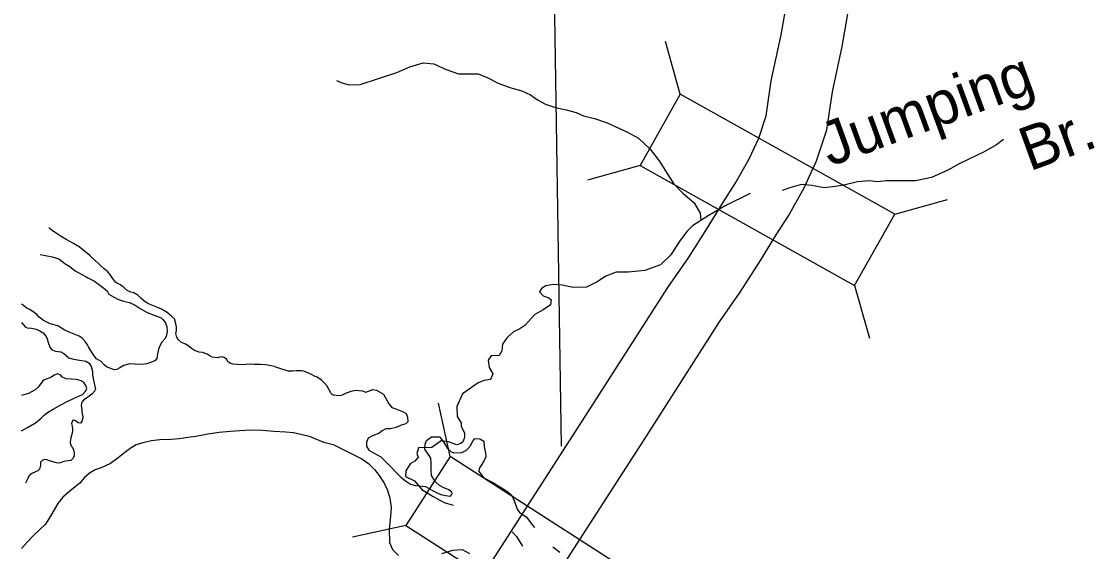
# Model space of a CAD drawing. Extents: x -492261 to -432772, y 1441225 to 1452922.
# Drawn here: x -459921.4 to -459791.8, y 1451627.3 to 1451691.4 of the extents above; entities that cross this region are included whole.
import ezdxf

# ---------------------------------------------------------------- set-up
doc = ezdxf.new("R2010")
doc.units = 0
doc.layers.add('Default', color=7, linetype='Continuous')

msp = doc.modelspace()

# ---------------------------------------------------------------- linework, layer by layer
at = {"layer": 'Default'}
for p, q in [((-459841.83, 1451682.61), (-459843.61, 1451688.97)), ((-459846.67, 1451673.98), (-459853.03, 1451672.2)), ((-459815.93, 1451668.07), (-459809.57, 1451669.86)), ((-459820.77, 1451659.44), (-459818.99, 1451653.09)), ((-459869.64, 1451638.77), (-459871.05, 1451645.22)), ((-459874.99, 1451630.44), (-459881.44, 1451629.03))]:
    msp.add_line(p, q, dxfattribs=at)
for points in [[(-459856.2, 1451640.04), (-459857.13, 1451699.95), (-459857.07, 1451700.88), (-459857.88, 1451764.63), (-459857.72, 1451765.56), (-459857.84, 1451829.92), (-459857.78, 1451831.18), (-459858.68, 1451894.27)], [(-459880.67, 1451586.99), (-459870.99, 1451602.58), (-459862.3, 1451615.79), (-459845.93, 1451641.25), (-459837.1, 1451655.06), (-459834.61, 1451658.63), (-459832.16, 1451662.47), (-459830.27, 1451665.59), (-459828.78, 1451667.87), (-459826.87, 1451671.27), (-459825.36, 1451674.52), (-459824.12, 1451678.26), (-459823.46, 1451682.88), (-459822.28, 1451688.35), (-459819.61, 1451703.72), (-459814.06, 1451738.82), (-459808.56, 1451770.84), (-459804.54, 1451796.57), (-459800.12, 1451821.52)], [(-459887.04, 1451590.94), (-459877.31, 1451606.62), (-459868.59, 1451619.88), (-459852.25, 1451645.3), (-459843.34, 1451659.22), (-459840.85, 1451662.79), (-459838.53, 1451666.43), (-459836.62, 1451669.59), (-459835.19, 1451671.77), (-459833.55, 1451674.68), (-459832.35, 1451677.28), (-459831.45, 1451679.99), (-459830.85, 1451684.2), (-459829.65, 1451689.78), (-459827, 1451704.95), (-459821.46, 1451740.04), (-459815.96, 1451772.06), (-459811.94, 1451797.8)], [(-459883.37, 1451684.26), (-459882.71, 1451683.95), (-459881.83, 1451683.72), (-459880.51, 1451683.78), (-459876.07, 1451685.22), (-459874.51, 1451685.88), (-459872.88, 1451686.4), (-459871.6, 1451686.25), (-459870.11, 1451685.56), (-459868.64, 1451685.07), (-459866.27, 1451685.06), (-459865.18, 1451684.61), (-459863.82, 1451683.91), (-459862.43, 1451683.4), (-459860.99, 1451682.98), (-459859.93, 1451682.53), (-459859.09, 1451681.9), (-459858.1, 1451681.4), (-459856.89, 1451680.98), (-459855.61, 1451680.71), (-459854.43, 1451680.36), (-459853.52, 1451679.98), (-459852.19, 1451679.66), (-459850.65, 1451679.13), (-459848.2, 1451678.01), (-459846.88, 1451677.26), (-459845.47, 1451675.94), (-459844.39, 1451674.52), (-459842.67, 1451671.78), (-459841.51, 1451670.6), (-459840.16, 1451669.46), (-459839.43, 1451668.22), (-459839.34, 1451667.32)], [(-459802.78, 1451677.12), (-459803.64, 1451676.45), (-459805.14, 1451675.61), (-459808.16, 1451674.18), (-459809.51, 1451673.4), (-459811.47, 1451672.52), (-459813.43, 1451672.1), (-459816.98, 1451672.11), (-459818, 1451672.01), (-459818.98, 1451672.11), (-459820.43, 1451671.97), (-459821.92, 1451671.61), (-459823.11, 1451671.41), (-459824.46, 1451671.27), (-459825.96, 1451671.54), (-459827.19, 1451671.66), (-459828.61, 1451671.27), (-459829.51, 1451670.95)], [(-459833.39, 1451670.58), (-459836.42, 1451669.1), (-459838.46, 1451667.89), (-459840.34, 1451666.67), (-459841.05, 1451665.98), (-459841.99, 1451664.73), (-459842.98, 1451663.17), (-459844.23, 1451661.97), (-459846.11, 1451661.27), (-459848.13, 1451661.07), (-459849.6, 1451661.08), (-459850.84, 1451660.6), (-459851.87, 1451659.9), (-459853.18, 1451659.26), (-459854.78, 1451659.23), (-459856.09, 1451659.49), (-459857.19, 1451659.57), (-459858.06, 1451659.4), (-459858.6, 1451659.08), (-459858.84, 1451658.7), (-459858.41, 1451658.21), (-459857.72, 1451657.97), (-459857.44, 1451657.71), (-459857.5, 1451657.13), (-459858.39, 1451656.51), (-459859.4, 1451655.93), (-459860.62, 1451654.62), (-459861.21, 1451654.23), (-459861.97, 1451653.84), (-459862.75, 1451653.16), (-459863.31, 1451652.37), (-459863.39, 1451651.57), (-459863.73, 1451650.99), (-459864.67, 1451650.96), (-459865.06, 1451650.43), (-459864.92, 1451649.55), (-459864.5, 1451648.79), (-459864.75, 1451648.1), (-459865.55, 1451647.96), (-459866.27, 1451647.69), (-459868.14, 1451646.34), (-459868.84, 1451644.82)], [(-459883.99, 1451646.38), (-459884.5, 1451647.26), (-459884.8, 1451647.64), (-459885.17, 1451648), (-459885.71, 1451648.35), (-459885.94, 1451648.45), (-459886.37, 1451648.69), (-459887.33, 1451649.08), (-459887.6, 1451649.14), (-459887.96, 1451649.12), (-459888.23, 1451649.12), (-459888.64, 1451649.1), (-459889.2, 1451649.09), (-459890.7, 1451649.58), (-459890.91, 1451649.65), (-459891.25, 1451649.74), (-459891.66, 1451649.83), (-459891.92, 1451649.87), (-459892.55, 1451649.89), (-459893.3, 1451649.91), (-459893.76, 1451649.93), (-459894.27, 1451649.92), (-459894.8, 1451649.87), (-459895.31, 1451649.9), (-459895.88, 1451649.95), (-459896.22, 1451650.06), (-459896.4, 1451650.17), (-459896.52, 1451650.32), (-459896.63, 1451650.49), (-459896.85, 1451650.71), (-459897.13, 1451650.81), (-459897.45, 1451650.77), (-459897.7, 1451650.69), (-459898.38, 1451650.78), (-459898.68, 1451650.94), (-459898.98, 1451651.16), (-459899.55, 1451651.35), (-459899.97, 1451651.4), (-459900.51, 1451651.58), (-459900.88, 1451651.82), (-459901.22, 1451652.11), (-459901.7, 1451652.4), (-459902.08, 1451652.57), (-459902.46, 1451652.87), (-459902.59, 1451653.03), (-459902.7, 1451653.34), (-459902.76, 1451653.64), (-459902.71, 1451654.01), (-459902.71, 1451654.46), (-459902.77, 1451654.83), (-459902.92, 1451655.42), (-459903.28, 1451655.73), (-459903.84, 1451656.19), (-459904.5, 1451656.61), (-459905.06, 1451656.84), (-459905.68, 1451657.08), (-459906.07, 1451657.24), (-459906.49, 1451657.46), (-459906.96, 1451657.89), (-459907.37, 1451658.29), (-459907.85, 1451658.56), (-459908.22, 1451658.63), (-459908.65, 1451658.84), (-459909.07, 1451659.2), (-459909.47, 1451659.54), (-459909.83, 1451659.7), (-459910.05, 1451659.87), (-459910.29, 1451660.18), (-459910.5, 1451660.47), (-459910.75, 1451660.83), (-459911.03, 1451661.14), (-459911.45, 1451661.48), (-459911.8, 1451661.78), (-459912.07, 1451662.09), (-459912.42, 1451662.39), (-459912.84, 1451662.77), (-459913.18, 1451663.09), (-459913.82, 1451663.61), (-459914.45, 1451664.12), (-459915.15, 1451664.53), (-459916.01, 1451665.01), (-459916.63, 1451665.39), (-459917.11, 1451665.69), (-459917.68, 1451666.08), (-459917.95, 1451666.32), (-459918.11, 1451666.45)], [(-459919.15, 1451663.21), (-459918.71, 1451663.13), (-459917.73, 1451662.91), (-459916.89, 1451662.66), (-459916.18, 1451662.12), (-459915.58, 1451661.74), (-459914.94, 1451661.21), (-459913.62, 1451660.5), (-459913.4, 1451660.38), (-459912.61, 1451659.97), (-459911.63, 1451659.27), (-459911.06, 1451658.82), (-459910.86, 1451658.42), (-459910.31, 1451658.07), (-459909.72, 1451657.75), (-459909.08, 1451657.54), (-459908.39, 1451657.39), (-459907.7, 1451657.06), (-459907.09, 1451656.67), (-459906.23, 1451656.18), (-459905.39, 1451655.87), (-459904.55, 1451655.54), (-459904.34, 1451655.33), (-459904.03, 1451654.94), (-459903.88, 1451654.44), (-459903.82, 1451653.88), (-459903.96, 1451653.29), (-459904.11, 1451653.01), (-459904.48, 1451652.61), (-459904.82, 1451651.9), (-459904.98, 1451651.17), (-459905.08, 1451650.64), (-459905.32, 1451650.33), (-459905.83, 1451650.13), (-459906.29, 1451650), (-459906.91, 1451649.91), (-459907.71, 1451649.93), (-459908.36, 1451649.97), (-459909.06, 1451649.79), (-459909.54, 1451649.48), (-459909.9, 1451649.31), (-459910.21, 1451649.26), (-459910.62, 1451649.4), (-459911.14, 1451649.61), (-459911.42, 1451649.87), (-459911.8, 1451650.25), (-459912.37, 1451650.59), (-459912.66, 1451650.96)], [(-459912.66, 1451650.96), (-459913.08, 1451651.63), (-459913.32, 1451652.02), (-459913.45, 1451652.29), (-459913.72, 1451652.67), (-459914.09, 1451653.08), (-459914.46, 1451653.32), (-459915.06, 1451653.58), (-459915.66, 1451653.79), (-459916.27, 1451654.08), (-459917.05, 1451654.57), (-459917.96, 1451654.81), (-459918.78, 1451655.23), (-459919.29, 1451655.61), (-459919.57, 1451655.93), (-459920.03, 1451656.32), (-459920.46, 1451656.55), (-459920.79, 1451656.73), (-459921.18, 1451657.02), (-459921.42, 1451657.2)], [(-459921.42, 1451655), (-459921.38, 1451654.95), (-459920.98, 1451654.47), (-459920.73, 1451654.35), (-459920.23, 1451654.31), (-459919.64, 1451654.17), (-459919.21, 1451653.99), (-459918.88, 1451653.77), (-459918.82, 1451653.72), (-459918.42, 1451653.28), (-459918.33, 1451652.99), (-459918.18, 1451652.57), (-459917.98, 1451652), (-459917.76, 1451651.66), (-459917.33, 1451651.51), (-459916.66, 1451651.44), (-459916.32, 1451651.25), (-459916.02, 1451650.97), (-459915.69, 1451650.72), (-459915.29, 1451650.57), (-459914.64, 1451650.45), (-459913.63, 1451650.32), (-459913.24, 1451650.08), (-459913, 1451649.65), (-459912.85, 1451649.04), (-459912.83, 1451648.67), (-459912.78, 1451648.21), (-459912.47, 1451646.87), (-459912.58, 1451646.71), (-459912.92, 1451646.33), (-459913.23, 1451646.07), (-459913.58, 1451645.83), (-459913.88, 1451645.63), (-459914.12, 1451645.35), (-459914.23, 1451645.01), (-459914.15, 1451644.32), (-459914.12, 1451644.17), (-459914, 1451643.56), (-459914.03, 1451643.27), (-459914.12, 1451643.02), (-459914.3, 1451642.82), (-459914.56, 1451642.84), (-459914.75, 1451642.97), (-459914.89, 1451643.07), (-459915.13, 1451643.17), (-459915.24, 1451643.08), (-459915.37, 1451642.76), (-459915.29, 1451642.44), (-459915.24, 1451642.09), (-459915.27, 1451641.76), (-459915.45, 1451641.05), (-459915.52, 1451640.55), (-459915.5, 1451640.2), (-459915.39, 1451640.04), (-459915.28, 1451639.88), (-459915.19, 1451639.7), (-459915.09, 1451639.43), (-459915.05, 1451639.24), (-459915.04, 1451638.87), (-459915.16, 1451638.59), (-459915.46, 1451638.3), (-459916.1, 1451638.21), (-459916.41, 1451638.11), (-459916.83, 1451637.96), (-459917.18, 1451638.01), (-459917.65, 1451638.11), (-459918.03, 1451638.25), (-459918.35, 1451638.38), (-459918.67, 1451638.4), (-459918.91, 1451638.28), (-459919.11, 1451638.09), (-459919.13, 1451637.71), (-459919.26, 1451637.23), (-459919.45, 1451637.04), (-459920.09, 1451636.77), (-459920.35, 1451636.63), (-459920.53, 1451636.4), (-459920.66, 1451636.11), (-459920.92, 1451635.56)], [(-459915.12, 1451645.79), (-459914.07, 1451646.28), (-459913.64, 1451646.73), (-459913.52, 1451646.98), (-459913.66, 1451647.38), (-459913.86, 1451647.7), (-459914.21, 1451647.93), (-459914.77, 1451648.09), (-459915.42, 1451648.13), (-459916.03, 1451648.17), (-459916.54, 1451648.41), (-459916.66, 1451648.63), (-459917.05, 1451648.78), (-459917.47, 1451648.62), (-459917.8, 1451648.35), (-459918.63, 1451648.06), (-459918.86, 1451647.93), (-459919.41, 1451647.16), (-459919.76, 1451646.82), (-459920.57, 1451646.41), (-459921.42, 1451646.17)], [(-459883.99, 1451646.38), (-459883.77, 1451646.23), (-459883.42, 1451646.18), (-459883.08, 1451646.16), (-459882.64, 1451646.24), (-459882.24, 1451646.42), (-459881.59, 1451646.69), (-459881.06, 1451646.81), (-459880.26, 1451646.71), (-459879.81, 1451646.54), (-459879.48, 1451646.69), (-459878.96, 1451646.87), (-459878.53, 1451646.81), (-459877.68, 1451646.31), (-459877.44, 1451645.88), (-459877.04, 1451645.15), (-459876.68, 1451644.7), (-459876.19, 1451644.53), (-459875.41, 1451644.23), (-459874.95, 1451643.98), (-459874.8, 1451643.54), (-459874.73, 1451642.98), (-459874.97, 1451642.71), (-459875.56, 1451642.56), (-459876.14, 1451642.3), (-459876.86, 1451642.12), (-459877.41, 1451642.12), (-459877.84, 1451641.87), (-459878.24, 1451641.56), (-459878.93, 1451641.33), (-459879.54, 1451641), (-459879.76, 1451640.5), (-459879.75, 1451640.04), (-459879.45, 1451639.55), (-459878.91, 1451639.2), (-459878.02, 1451638.72), (-459877.28, 1451638.01), (-459876.73, 1451637.44), (-459876.12, 1451636.8), (-459875.61, 1451636.29), (-459875.02, 1451635.84), (-459874.41, 1451635.44), (-459873.82, 1451635.26), (-459872.61, 1451635.15), (-459871.78, 1451634.66), (-459871.19, 1451634.39), (-459870.77, 1451634.18), (-459870.18, 1451634.05), (-459869.6, 1451633.99), (-459869.48, 1451634.12), (-459869.38, 1451634.3), (-459869.45, 1451634.45), (-459869.8, 1451634.73), (-459870.49, 1451635.03), (-459870.93, 1451635.28), (-459871.44, 1451635.77), (-459871.87, 1451636.49), (-459871.94, 1451637.14), (-459871.93, 1451637.97), (-459871.95, 1451638.57), (-459872.27, 1451639.02), (-459872.7, 1451639.65), (-459872.67, 1451640.26), (-459872.48, 1451640.69), (-459871.87, 1451641.17), (-459870.93, 1451641.15), (-459870.44, 1451640.56), (-459869.96, 1451639.75), (-459869.51, 1451639.35), (-459869.28, 1451639.25), (-459869.18, 1451639.22), (-459868.22, 1451639.27), (-459867.66, 1451639.53), (-459867.21, 1451640.02), (-459866.88, 1451640.61), (-459866.65, 1451640.97), (-459866.04, 1451640.92), (-459865.55, 1451640.63), (-459865.53, 1451639.96), (-459865.37, 1451639.23), (-459865.32, 1451638.73), (-459865.57, 1451638.2), (-459865.94, 1451637.64), (-459866.14, 1451637.33), (-459866.19, 1451636.94), (-459865.55, 1451636.19), (-459864.47, 1451635.61), (-459863.77, 1451635.2), (-459863.02, 1451634.74), (-459862.67, 1451634.5), (-459862.17, 1451634.06), (-459861.86, 1451633.34), (-459861.53, 1451632.4), (-459861.25, 1451631.99), (-459860.45, 1451631.48), (-459860.14, 1451631.07), (-459859.72, 1451630.52), (-459859.44, 1451630.17)], [(-459921.42, 1451641.89), (-459920.68, 1451642.27), (-459919.71, 1451642.83), (-459919.03, 1451643.43), (-459918.65, 1451643.83), (-459918.26, 1451644.09), (-459917.58, 1451644.51), (-459916.67, 1451645.03), (-459915.91, 1451645.41), (-459915.12, 1451645.79)], [(-459868.84, 1451644.82), (-459868.79, 1451643.62), (-459868.3, 1451642.85), (-459868.3, 1451642.39), (-459867.9, 1451641.64), (-459867.9, 1451641.15), (-459867.96, 1451640.94), (-459868.11, 1451640.53), (-459868.33, 1451640.36), (-459868.84, 1451640.19), (-459869.84, 1451640.56), (-459870.72, 1451640.66), (-459871.85, 1451639.88), (-459873.47, 1451639.84), (-459873.68, 1451639.14), (-459873.52, 1451638.69), (-459873.91, 1451638.2), (-459874.47, 1451637.89), (-459875, 1451637.05), (-459875.04, 1451636.35), (-459873.95, 1451635.82), (-459873.07, 1451634.77), (-459871.7, 1451633.92), (-459870.34, 1451633.23), (-459869.26, 1451632.88)], [(-459883.61, 1451640.16), (-459884.91, 1451640.47), (-459886.5, 1451641.15), (-459887.68, 1451641.44), (-459888.57, 1451641.64), (-459889.47, 1451641.73), (-459890.93, 1451641.81), (-459892.29, 1451641.92), (-459893.82, 1451641.96), (-459895.06, 1451641.88), (-459896.16, 1451641.78), (-459897.55, 1451641.66), (-459898.89, 1451641.47), (-459900.37, 1451641.21), (-459901.31, 1451641.09), (-459902.37, 1451640.9), (-459903.33, 1451640.83), (-459904.71, 1451640.78), (-459905.73, 1451640.65), (-459906.77, 1451640.44), (-459907.55, 1451640.2), (-459908.18, 1451639.84), (-459908.93, 1451639.25), (-459909.75, 1451638.63), (-459910.67, 1451637.93), (-459911.79, 1451637.39), (-459912.51, 1451637.18), (-459913.22, 1451636.77), (-459913.83, 1451636.18), (-459914.39, 1451635.54), (-459915.34, 1451634.77), (-459916.41, 1451633.87), (-459917.03, 1451633.11), (-459917.76, 1451631.86), (-459918.5, 1451630.58), (-459919.26, 1451629.89), (-459919.99, 1451629.19), (-459920.73, 1451628.41), (-459921.42, 1451627.63)], [(-459883.61, 1451640.16), (-459881.67, 1451639.19), (-459880.3, 1451638.51), (-459879.5, 1451637.91), (-459878.79, 1451637.19), (-459878.22, 1451636.46), (-459877.7, 1451635.68), (-459877.25, 1451634.84), (-459876.93, 1451633.74), (-459876.78, 1451632.63), (-459876.86, 1451631.54), (-459877, 1451629.99), (-459876.95, 1451628.38), (-459876.59, 1451627.52), (-459875.88, 1451626.8)], [(-459862.13, 1451629.66), (-459861.61, 1451629.08), (-459860.9, 1451627.95)], [(-459870.64, 1451627.04), (-459869.31, 1451627.43), (-459868.19, 1451627.52), (-459867.29, 1451627.05)], [(-459857.24, 1451627.83), (-459856.4, 1451627.22)]]:
    msp.add_lwpolyline(points, dxfattribs=at)
for points in [[(-459815.93, 1451668.07), (-459841.83, 1451682.61), (-459846.67, 1451673.98), (-459820.77, 1451659.44)], [(-459844.66, 1451622.71), (-459869.64, 1451638.77), (-459874.99, 1451630.44), (-459850.01, 1451614.38)]]:
    msp.add_lwpolyline(points, close=True, dxfattribs=at)

# ---------------------------------------------------------------- texts
for s, p in [('Jumping', (-459823.77, 1451673.81)), ('Br.', (-459799.66, 1451673.23))]:
    msp.add_text(s, height=5.28, rotation=20, dxfattribs=at).set_placement(p)

doc.saveas('drawing.dxf')
